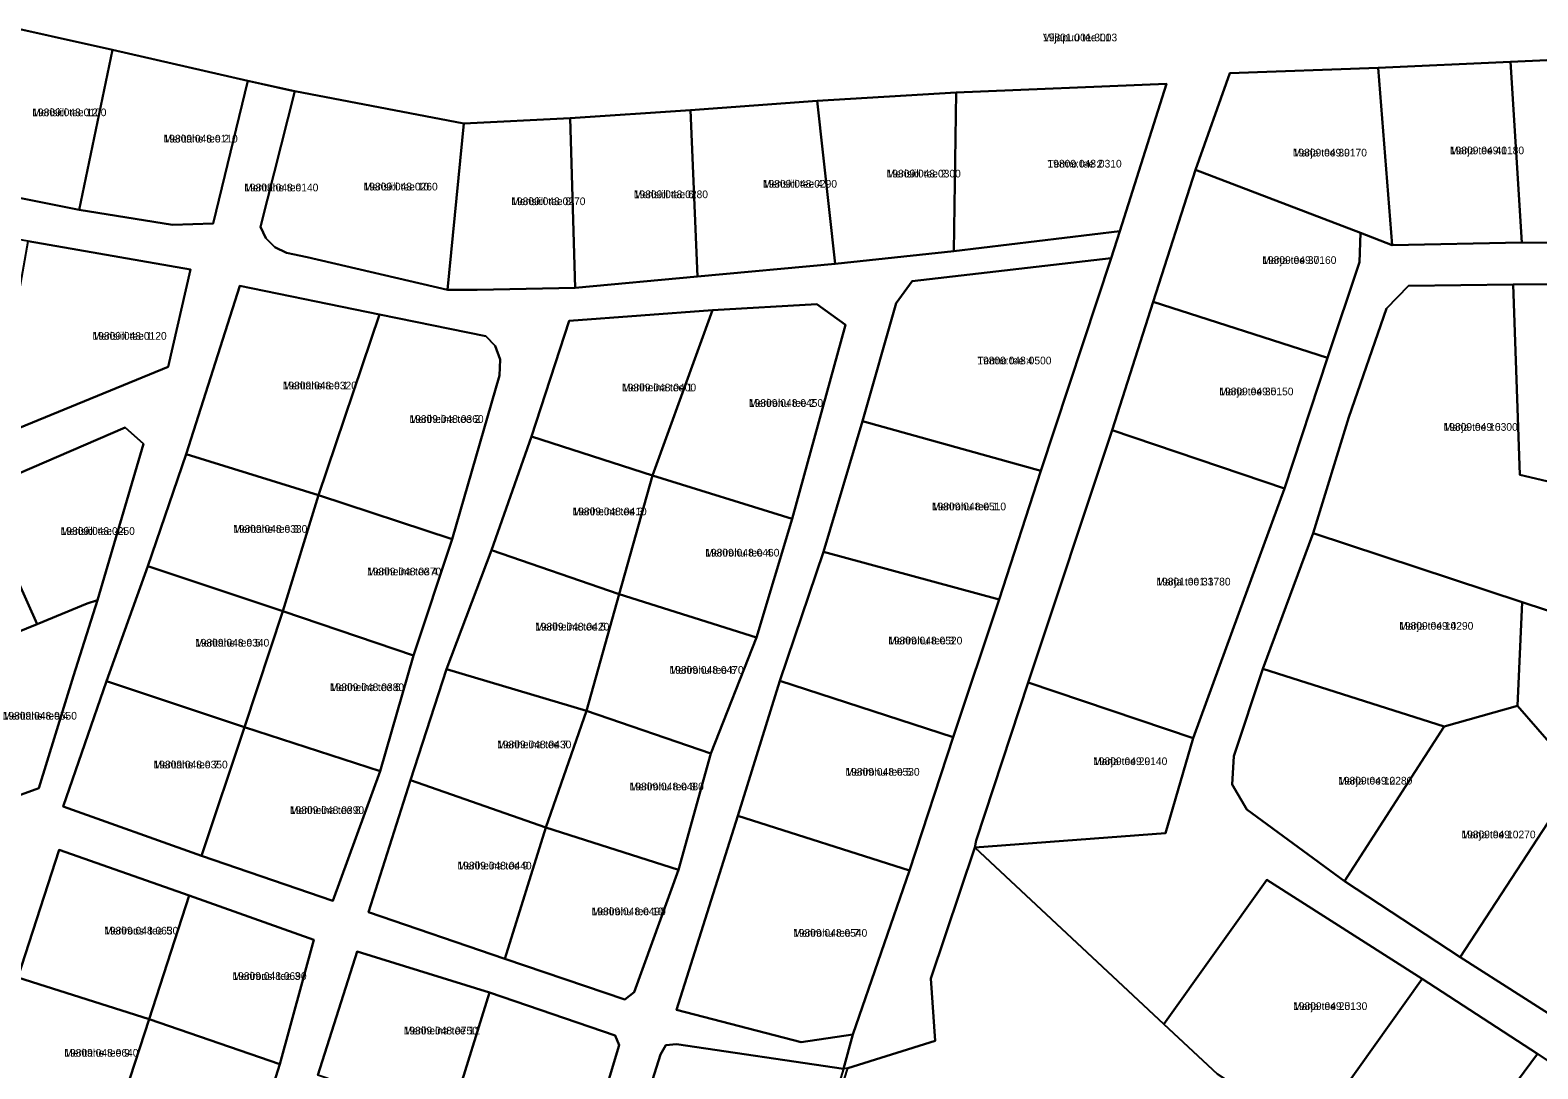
# Model space of a CAD drawing. Extents: x 516875 to 535633, y 6574491 to 6593094.
# Drawn here: x 522233.5 to 522528.1, y 6588191.7 to 6588394.7 of the extents above; entities that cross this region are included whole.
import ezdxf

# ---------------------------------------------------------------- set-up
doc = ezdxf.new("R2010")
doc.units = 0
for name, color, linetype in [('L_AADRESS', 7, 'Continuous'), ('PIIR', 7, 'Continuous'), ('TUNNUS', 7, 'Continuous')]:
    doc.layers.add(name, color=color, linetype=linetype)

msp = doc.modelspace()

# ---------------------------------------------------------------- linework, layer by layer
at = {"layer": 'PIIR'}
for points in [[(522249.57, 6588390.88), (522243.06, 6588359.61), (522218.17, 6588364.58), (522224.93, 6588396.36)], [(522276, 6588384.8), (522269.26, 6588356.94), (522261.26, 6588356.67), (522243.06, 6588359.61), (522249.57, 6588390.88)], [(522496.89, 6588387.39), (522522.77, 6588388.55), (522524.95, 6588353.22), (522499.62, 6588352.68)], [(522522.77, 6588388.55), (522548.44, 6588389.73), (522551.07, 6588353.04), (522524.95, 6588353.22)], [(522467.91, 6588386.33), (522496.89, 6588387.39), (522499.62, 6588352.68), (522493.42, 6588355.13), (522461.23, 6588367.4)], [(522318.24, 6588376.48), (522315, 6588344), (522287.58, 6588350.37), (522283.56, 6588351.23), (522281.27, 6588352.31), (522279.55, 6588354.09), (522278.5, 6588356.32), (522285.17, 6588382.81)], [(522414, 6588351.55), (522390.78, 6588349.05), (522387.29, 6588380.94), (522414.4, 6588382.55)], [(522446.39, 6588355.42), (522414, 6588351.55), (522414.4, 6588382.55), (522455.55, 6588384.21)], [(522390.78, 6588349.05), (522363.88, 6588346.55), (522362.52, 6588379.12), (522387.29, 6588380.94)], [(522315, 6588344), (522318.24, 6588376.48), (522338.97, 6588377.53), (522339.97, 6588344.35), (522320.79, 6588343.98)], [(522362.52, 6588379.12), (522363.88, 6588346.55), (522339.97, 6588344.35), (522338.97, 6588377.53)], [(522461.23, 6588367.4), (522493.42, 6588355.13), (522493.24, 6588349.37), (522487.01, 6588330.69), (522452.95, 6588341.6)], [(522132.7, 6588307.34), (522118.27, 6588284.12), (522132.35, 6588272.62), (522161.72, 6588286.42), (522173.79, 6588291.9), (522172.07, 6588307.93), (522187.34, 6588317.56), (522191.17, 6588319.3), (522197.1, 6588302.61), (522206.77, 6588307.61), (522223.48, 6588313.81), (522226.22, 6588314.93), (522260.43, 6588328.94), (522264.83, 6588347.96), (522233.05, 6588353.51), (522189.84, 6588360.99), (522173.11, 6588364.66), (522171.69, 6588364.32), (522169.41, 6588361.54), (522154.49, 6588339.57), (522144.96, 6588325.31)], [(522264.83, 6588347.96), (522260.43, 6588328.94), (522226.22, 6588314.93), (522233.05, 6588353.51)], [(522444.7, 6588350.19), (522430.95, 6588308.63), (522396.12, 6588318.29), (522402.69, 6588341.36), (522405.82, 6588345.64)], [(522301.72, 6588339.17), (522274.41, 6588344.78), (522263.93, 6588311.83), (522256.45, 6588290), (522248.4, 6588267.5), (522239.91, 6588242.98), (522266.93, 6588233.39), (522292.59, 6588224.56), (522301.85, 6588249.94), (522308.4, 6588272.5), (522315.91, 6588295.23), (522325.21, 6588327.21), (522325.32, 6588330.37), (522324.36, 6588333.01), (522322.5, 6588334.91)], [(522301.72, 6588339.17), (522289.84, 6588303.85), (522263.93, 6588311.83), (522274.41, 6588344.78)], [(522491.19, 6588319.06), (522498.51, 6588340.36), (522502.82, 6588344.76), (522523.3, 6588345.01), (522524.6, 6588307.82), (522535.15, 6588305.34), (522533.95, 6588279.98), (522525.04, 6588282.94), (522484.21, 6588296.45)], [(522524.6, 6588307.82), (522523.3, 6588345.01), (522549.42, 6588345.24), (522549.34, 6588312.06), (522535.15, 6588305.34)], [(522452.95, 6588341.6), (522487.01, 6588330.69), (522478.62, 6588305.14), (522444.91, 6588316.56)], [(522322.5, 6588334.91), (522324.36, 6588333.01), (522325.32, 6588330.37), (522325.21, 6588327.21), (522315.91, 6588295.23), (522289.84, 6588303.85), (522301.72, 6588339.17)], [(522366.83, 6588339.97), (522338.78, 6588337.94), (522331.42, 6588315.33), (522323.64, 6588293.13), (522314.86, 6588269.84), (522307.8, 6588248.18), (522299.61, 6588222.36), (522326.23, 6588213.22), (522349.68, 6588205.26), (522351.52, 6588206.7), (522360.15, 6588230.65), (522366.48, 6588253.36), (522375.38, 6588276.03), (522382.37, 6588299.22), (522392.79, 6588337.11), (522387.23, 6588341.18)], [(522366.83, 6588339.97), (522355.06, 6588307.68), (522331.42, 6588315.33), (522338.78, 6588337.94)], [(522387.23, 6588341.18), (522392.79, 6588337.11), (522382.37, 6588299.22), (522355.06, 6588307.68), (522366.83, 6588339.97)], [(522430.95, 6588308.63), (522422.84, 6588283.49), (522388.49, 6588292.79), (522396.12, 6588318.29)], [(522255.64, 6588313.9), (522246.62, 6588283.32), (522244.6, 6588282.7), (522234.84, 6588278.67), (522223.2, 6588304.62), (522252.05, 6588317.08)], [(522355.06, 6588307.68), (522348.57, 6588284.52), (522323.64, 6588293.13), (522331.42, 6588315.33)], [(522444.91, 6588316.56), (522478.62, 6588305.14), (522469.68, 6588280.76), (522460.75, 6588256.35), (522428.5, 6588267.23)], [(522289.84, 6588303.85), (522282.86, 6588281.18), (522256.45, 6588290), (522263.93, 6588311.83)], [(522382.37, 6588299.22), (522375.38, 6588276.03), (522348.57, 6588284.52), (522355.06, 6588307.68)], [(522234.84, 6588278.67), (522212.17, 6588269.45), (522200.25, 6588295.23), (522223.2, 6588304.62)], [(522315.91, 6588295.23), (522308.4, 6588272.5), (522282.86, 6588281.18), (522289.84, 6588303.85)], [(522484.21, 6588296.45), (522525.04, 6588282.94), (522524.13, 6588262.7), (522509.78, 6588258.67), (522474.39, 6588269.93)], [(522348.57, 6588284.52), (522342.16, 6588261.67), (522314.86, 6588269.84), (522323.64, 6588293.13)], [(522422.84, 6588283.49), (522413.85, 6588256.58), (522379.99, 6588267.58), (522388.49, 6588292.79)], [(522282.86, 6588281.18), (522275.36, 6588258.51), (522248.4, 6588267.5), (522256.45, 6588290)], [(522212.17, 6588269.45), (522234.84, 6588278.67), (522244.6, 6588282.7), (522246.62, 6588283.32), (522241.95, 6588268.51), (522235.19, 6588246.62), (522220.83, 6588241.4), (522209.58, 6588268.26)], [(522375.38, 6588276.03), (522366.48, 6588253.36), (522342.16, 6588261.67), (522348.57, 6588284.52)], [(522308.4, 6588272.5), (522301.85, 6588249.94), (522275.36, 6588258.51), (522282.86, 6588281.18)], [(522342.16, 6588261.67), (522334.24, 6588238.91), (522307.8, 6588248.18), (522314.86, 6588269.84)], [(522468.38, 6588247.28), (522468.71, 6588252.86), (522474.39, 6588269.93), (522509.78, 6588258.67), (522490.3, 6588228.44), (522471.24, 6588242.42)], [(522275.36, 6588258.51), (522266.93, 6588233.39), (522239.91, 6588242.98), (522248.4, 6588267.5)], [(522413.85, 6588256.58), (522405.33, 6588230.48), (522371.74, 6588241.17), (522379.99, 6588267.58)], [(522418.34, 6588236.39), (522428.5, 6588267.23), (522460.75, 6588256.35), (522455.32, 6588237.79), (522418.09, 6588234.97)], [(522490.3, 6588228.44), (522509.78, 6588258.67), (522524.13, 6588262.7), (522536.04, 6588248.98), (522512.92, 6588213.58)], [(522366.48, 6588253.36), (522360.15, 6588230.65), (522334.24, 6588238.91), (522342.16, 6588261.67)], [(522301.85, 6588249.94), (522292.59, 6588224.56), (522266.93, 6588233.39), (522275.36, 6588258.51)], [(522334.24, 6588238.91), (522326.23, 6588213.22), (522299.61, 6588222.36), (522307.8, 6588248.18)], [(522536.04, 6588248.98), (522539.66, 6588237.58), (522544.93, 6588231.05), (522553.71, 6588225.17), (522537, 6588198.18), (522512.92, 6588213.58)], [(522405.33, 6588230.48), (522394.27, 6588198.42), (522384.14, 6588196.97), (522359.8, 6588203.28), (522371.74, 6588241.17)], [(522360.15, 6588230.65), (522351.52, 6588206.7), (522349.68, 6588205.26), (522326.23, 6588213.22), (522334.24, 6588238.91)], [(522264.52, 6588225.6), (522256.75, 6588201.43), (522231.06, 6588209.59), (522239.11, 6588234.54)], [(522455.03, 6588200.48), (522475.16, 6588228.69), (522505.52, 6588209.32), (522483.73, 6588178.8), (522479.92, 6588181.28), (522465.48, 6588190.72)], [(522288.89, 6588216.97), (522282.26, 6588192.63), (522256.75, 6588201.43), (522264.52, 6588225.6)], [(522323.25, 6588206.64), (522316.39, 6588184.62), (522315.56, 6588182.5), (522314.07, 6588182.25), (522289.67, 6588190.49), (522297.38, 6588214.66)], [(522256.75, 6588201.43), (522249.29, 6588178.66), (522223.53, 6588187), (522231.06, 6588209.59)], [(522505.52, 6588209.32), (522528.02, 6588194.66), (522505.71, 6588164.48), (522500.6, 6588167.81), (522483.73, 6588178.8)], [(522347.77, 6588198.26), (522348.59, 6588196.38), (522341.74, 6588173.66), (522318.86, 6588180.74), (522315.56, 6588182.5), (522316.39, 6588184.62), (522323.25, 6588206.64)], [(522282.26, 6588192.63), (522275.08, 6588169.92), (522249.29, 6588178.66), (522256.75, 6588201.43)], [(522359.79, 6588196.59), (522392.44, 6588191.74), (522391.62, 6588189.18), (522390.51, 6588185.71), (522382.81, 6588163.28), (522349.97, 6588173.33), (522356.65, 6588194.52), (522357.7, 6588196.38)], [(522505.71, 6588164.48), (522528.02, 6588194.66), (522561.21, 6588172.61), (522540.99, 6588141.27), (522537.95, 6588143.28), (522518.85, 6588155.97)]]:
    msp.add_lwpolyline(points, close=True, dxfattribs=at)
for points in [[(522548.44, 6588389.73), (522522.77, 6588388.55), (522496.89, 6588387.39), (522467.91, 6588386.33), (522461.23, 6588367.4), (522452.95, 6588341.6), (522444.91, 6588316.56), (522428.5, 6588267.23), (522418.34, 6588236.39), (522418.09, 6588234.97), (522409.5, 6588209.38), (522410.3, 6588197.22), (522393.23, 6588191.85), (522392.44, 6588191.74), (522394.27, 6588198.42), (522405.33, 6588230.48), (522413.85, 6588256.58), (522422.84, 6588283.49), (522430.95, 6588308.63), (522444.7, 6588350.19), (522446.39, 6588355.42), (522455.55, 6588384.21), (522414.4, 6588382.55), (522387.29, 6588380.94), (522362.52, 6588379.12), (522338.97, 6588377.53), (522318.24, 6588376.48), (522285.17, 6588382.81), (522276, 6588384.8), (522249.57, 6588390.88), (522224.93, 6588396.36)], [(522218.17, 6588364.58), (522243.06, 6588359.61), (522261.26, 6588356.67), (522269.26, 6588356.94), (522276, 6588384.8), (522284.42, 6588382.95), (522285.17, 6588382.81), (522278.5, 6588356.32), (522279.55, 6588354.09), (522281.27, 6588352.31), (522283.56, 6588351.23), (522287.58, 6588350.37), (522315, 6588344), (522320.79, 6588343.98), (522339.97, 6588344.35), (522363.88, 6588346.55), (522390.78, 6588349.05), (522414, 6588351.55), (522446.39, 6588355.42), (522444.7, 6588350.19), (522405.82, 6588345.64), (522402.69, 6588341.36), (522396.12, 6588318.29), (522388.49, 6588292.79), (522379.99, 6588267.58), (522371.74, 6588241.17), (522359.8, 6588203.28), (522384.14, 6588196.97), (522394.27, 6588198.42), (522392.44, 6588191.74), (522359.79, 6588196.59), (522357.7, 6588196.38), (522356.65, 6588194.52), (522349.97, 6588173.33)], [(522561.21, 6588172.61), (522528.02, 6588194.66), (522505.52, 6588209.32), (522475.16, 6588228.69), (522455.03, 6588200.48), (522418.09, 6588234.97), (522455.32, 6588237.79), (522460.75, 6588256.35), (522469.68, 6588280.76), (522478.62, 6588305.14), (522487.01, 6588330.69), (522493.24, 6588349.37), (522493.42, 6588355.13), (522499.62, 6588352.68), (522524.95, 6588353.22), (522551.07, 6588353.04)], [(522549.42, 6588345.24), (522523.3, 6588345.01), (522502.82, 6588344.76), (522498.51, 6588340.36), (522491.19, 6588319.06), (522484.21, 6588296.45), (522474.39, 6588269.93), (522468.71, 6588252.86), (522468.38, 6588247.28), (522471.24, 6588242.42), (522490.3, 6588228.44), (522512.92, 6588213.58), (522537, 6588198.18)], [(522220.83, 6588241.4), (522235.19, 6588246.62), (522241.95, 6588268.51), (522246.62, 6588283.32), (522255.64, 6588313.9), (522252.05, 6588317.08), (522223.2, 6588304.62)], [(522536.04, 6588248.98), (522524.13, 6588262.7), (522525.04, 6588282.94), (522533.95, 6588279.98)], [(522275.08, 6588169.92), (522282.26, 6588192.63), (522288.89, 6588216.97), (522264.52, 6588225.6), (522239.11, 6588234.54), (522231.06, 6588209.59)], [(522391.3, 6588185.82), (522393.23, 6588191.85), (522410.3, 6588197.22), (522409.5, 6588209.38), (522418.09, 6588234.97), (522455.03, 6588200.48), (522465.48, 6588190.72)], [(522341.74, 6588173.66), (522348.59, 6588196.38), (522347.77, 6588198.26), (522323.25, 6588206.64), (522297.38, 6588214.66), (522289.67, 6588190.49)]]:
    msp.add_lwpolyline(points, dxfattribs=at)

# ---------------------------------------------------------------- texts
at = {"layer": 'L_AADRESS'}
for s, p in [('Viljapuu tee L1', (522431.4, 6588392.55)), ('Merisiili tee 12', (522233.87, 6588377.91)), ('Meritähe tee 2', (522259.53, 6588372.77)), ('Marja tee 39', (522480.21, 6588370.04)), ('Marja tee 41', (522510.92, 6588370.47)), ('Termo tee 2', (522432.28, 6588367.88)), ('Merisiili tee 10', (522298.61, 6588363.4)), ('Merisiili tee 4', (522376.65, 6588363.95)), ('Merisiili tee 2', (522400.84, 6588365.94)), ('Meritähe tee', (522275.29, 6588363.22)), ('Merisiili tee 8', (522327.48, 6588360.53)), ('Merisiili tee 6', (522351.43, 6588361.89)), ('Marja tee 37', (522474.24, 6588349.04)), ('Merisiili tee 1', (522245.64, 6588334.22)), ('Termo tee 4', (522418.56, 6588329.41)), ('Meritähe tee 1', (522282.82, 6588324.53)), ('Meriheina tee 1', (522349.12, 6588324.14)), ('Marja tee 35', (522465.85, 6588323.37)), ('Merirohu tee 2', (522373.93, 6588321.11)), ('Meriheina tee 2', (522307.58, 6588317.98)), ('Marja tee 16', (522509.68, 6588316.43)), ('Meriheina tee 3', (522339.45, 6588299.92)), ('Merirohu tee 1', (522409.68, 6588300.89)), ('Merisiili tee 44', (522239.42, 6588296.09)), ('Meritähe tee 3', (522273.13, 6588296.5)), ('Merirohu tee 4', (522365.39, 6588291.86)), ('Meriheina tee 4', (522299.3, 6588288.18)), ('Marja tee 31', (522453.56, 6588286.2)), ('Meriheina tee 5', (522332.14, 6588277.4)), ('Marja tee 14', (522501.01, 6588277.56)), ('Meritähe tee 5', (522265.69, 6588274.26)), ('Merirohu tee 3', (522401.14, 6588274.68)), ('Merirohu tee 6', (522358.4, 6588268.94)), ('Meriheina tee 6', (522292.04, 6588265.56)), ('Meritähe tee 4', (522228.1, 6588259.99)), ('Meriheina tee 7', (522324.72, 6588254.38)), ('Meritähe tee 7', (522257.57, 6588250.45)), ('Merirohu tee 5', (522392.79, 6588249.03)), ('Marja tee 29', (522441.2, 6588251.1)), ('Merirohu tee 8', (522350.62, 6588246.16)), ('Marja tee 12', (522489.08, 6588247.3)), ('Meriheina tee 8', (522284.22, 6588241.54)), ('Marja tee 10', (522513.17, 6588236.79)), ('Meriheina tee 9', (522316.97, 6588230.7)), ('Merirohu tee 10', (522343.19, 6588221.76)), ('Meriroosi tee 5', (522247.92, 6588217.99)), ('Merirohu tee 7', (522382.56, 6588217.55)), ('Meriroosi tee 3', (522272.99, 6588209.12)), ('Marja tee 25', (522480.28, 6588203.24)), ('Meriheina tee 11', (522306.46, 6588198.46)), ('Meritähe tee 9', (522240.13, 6588194.12))]:
    msp.add_text(s, height=1.5, dxfattribs=at).set_placement(p)
at = {"layer": 'TUNNUS'}
for s, p in [('19801:001:3003', (522431.4, 6588392.55)), ('19809:048:0100', (522233.87, 6588377.91)), ('19809:048:0110', (522259.53, 6588372.77)), ('19809:049:0170', (522480.21, 6588370.04)), ('19809:049:0180', (522510.92, 6588370.47)), ('19809:048:0310', (522432.28, 6588367.88)), ('19809:048:0260', (522298.61, 6588363.4)), ('19809:048:0290', (522376.65, 6588363.95)), ('19809:048:0300', (522400.84, 6588365.94)), ('19809:048:0140', (522275.29, 6588363.22)), ('19809:048:0270', (522327.48, 6588360.53)), ('19809:048:0280', (522351.43, 6588361.89)), ('19809:049:0160', (522474.24, 6588349.04)), ('19809:048:0120', (522245.64, 6588334.22)), ('19809:048:0500', (522418.56, 6588329.41)), ('19809:048:0320', (522282.82, 6588324.53)), ('19809:048:0400', (522349.12, 6588324.14)), ('19809:049:0150', (522465.85, 6588323.37)), ('19809:048:0450', (522373.93, 6588321.11)), ('19809:048:0360', (522307.58, 6588317.98)), ('19809:049:0300', (522509.68, 6588316.43)), ('19809:048:0410', (522339.45, 6588299.92)), ('19809:048:0510', (522409.68, 6588300.89)), ('19809:048:0250', (522239.42, 6588296.09)), ('19809:048:0330', (522273.13, 6588296.5)), ('19809:048:0460', (522365.39, 6588291.86)), ('19809:048:0370', (522299.3, 6588288.18)), ('19801:001:3780', (522453.56, 6588286.2)), ('19809:048:0420', (522332.14, 6588277.4)), ('19809:049:0290', (522501.01, 6588277.56)), ('19809:048:0340', (522265.69, 6588274.26)), ('19809:048:0520', (522401.14, 6588274.68)), ('19809:048:0470', (522358.4, 6588268.94)), ('19809:048:0380', (522292.04, 6588265.56)), ('19809:048:0550', (522228.1, 6588259.99)), ('19809:048:0430', (522324.72, 6588254.38)), ('19809:048:0350', (522257.57, 6588250.45)), ('19809:048:0530', (522392.79, 6588249.03)), ('19809:049:0140', (522441.2, 6588251.1)), ('19809:048:0480', (522350.62, 6588246.16)), ('19809:049:0280', (522489.08, 6588247.3)), ('19809:048:0390', (522284.22, 6588241.54)), ('19809:049:0270', (522513.17, 6588236.79)), ('19809:048:0440', (522316.97, 6588230.7)), ('19809:048:0490', (522343.19, 6588221.76)), ('19809:048:0630', (522247.92, 6588217.99)), ('19809:048:0540', (522382.56, 6588217.55)), ('19809:048:0690', (522272.99, 6588209.12)), ('19809:049:0130', (522480.28, 6588203.24)), ('19809:048:0750', (522306.46, 6588198.46)), ('19809:048:0640', (522240.13, 6588194.12))]:
    msp.add_text(s, height=1.5, dxfattribs=at).set_placement(p)

doc.saveas('drawing.dxf')
